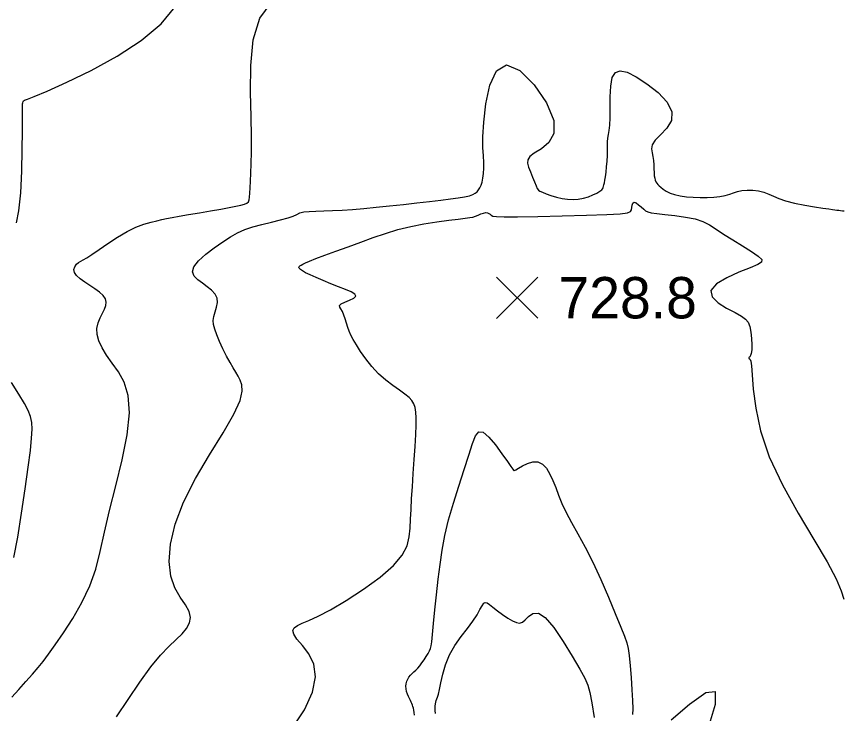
# Model space of a CAD drawing. Extents: x 2566142 to 2571431, y 418755 to 421584.
# Drawn here: x 2569642.8 to 2569942.6, y 420061.6 to 420314.2 of the extents above; entities that cross this region are included whole.
import ezdxf

# ---------------------------------------------------------------- set-up
doc = ezdxf.new("R2010")
doc.units = 0
for name, color, linetype in [('Contour_ADS_Major', 7, 'Continuous'), ('Contour_ADS_Minor', 7, 'Continuous'), ('Contour_ADS_Spot_Elevation', 7, 'Continuous')]:
    doc.layers.add(name, color=color, linetype=linetype)

# ---------------------------------------------------------------- blocks, each defined once
blk = doc.blocks.new('S750')
at = {"layer": 'Contour_ADS_Spot_Elevation'}
for p, q in [((-0.5, 0.498), (0.5, -0.498)), ((-0.498, -0.5), (0.498, 0.5))]:
    blk.add_line(p, q, dxfattribs=at)

msp = doc.modelspace()

# ---------------------------------------------------------------- linework, layer by layer
at = {"layer": 'Contour_ADS_Major'}
for points in [[(2569745.54, 420223.85), (2569745.97, 420224.12), (2569746.56, 420224.46), (2569747.51, 420224.92), (2569749.03, 420225.58), (2569751.35, 420226.5), (2569754.61, 420227.73), (2569758.61, 420229.2), (2569763.04, 420230.8), (2569767.63, 420232.46), (2569772.12, 420234.08), (2569776.57, 420235.6), (2569781.06, 420236.98), (2569785.7, 420238.17), (2569790.51, 420239.12), (2569795.22, 420239.87), (2569799.49, 420240.43), (2569802.98, 420240.83), (2569805.46, 420241.12), (2569807.12, 420241.34), (2569808.26, 420241.56), (2569809.2, 420241.85), (2569810.17, 420242.24), (2569811.17, 420242.65), (2569812.11, 420243), (2569812.93, 420243.18), (2569813.58, 420243.13), (2569814.09, 420242.89), (2569814.52, 420242.56), (2569814.94, 420242.2), (2569815.5, 420241.91), (2569816.81, 420241.69), (2569819.56, 420241.58), (2569824.46, 420241.59), (2569831.84, 420241.72), (2569840.64, 420241.95), (2569849.43, 420242.23), (2569856.78, 420242.51), (2569861.61, 420242.77), (2569864.26, 420243.08), (2569865.42, 420243.51), (2569865.76, 420244.13), (2569865.89, 420244.98), (2569866.01, 420245.87), (2569866.23, 420246.59), (2569866.68, 420246.91), (2569867.42, 420246.67), (2569868.35, 420246.03), (2569869.32, 420245.2), (2569870.19, 420244.4), (2569870.89, 420243.81), (2569871.68, 420243.39), (2569872.91, 420243.09), (2569874.92, 420242.81), (2569877.91, 420242.5), (2569881.54, 420242.1), (2569885.34, 420241.56), (2569888.82, 420240.84), (2569891.65, 420239.88), (2569894.07, 420238.67), (2569896.45, 420237.17), (2569899.18, 420235.37), (2569902.49, 420233.28), (2569906.02, 420231.09), (2569909.28, 420229.03), (2569911.75, 420227.32), (2569913.02, 420226.11), (2569912.96, 420225.2), (2569911.56, 420224.32), (2569908.77, 420223.17), (2569904.74, 420221.56), (2569900.33, 420219.55), (2569896.59, 420217.3), (2569894.56, 420214.95), (2569894.96, 420212.63), (2569897.17, 420210.45), (2569900.27, 420208.51), (2569903.33, 420206.89), (2569905.61, 420205.65), (2569907.12, 420204.57), (2569908.07, 420203.4), (2569908.65, 420201.88), (2569909.05, 420199.85), (2569909.3, 420197.53), (2569909.4, 420195.26), (2569909.35, 420193.36), (2569909.17, 420192.08), (2569908.91, 420191.33), (2569908.65, 420190.92), (2569908.44, 420190.7), (2569908.34, 420190.52), (2569908.35, 420190.35), (2569908.44, 420190.2), (2569908.59, 420190.09), (2569908.77, 420189.91), (2569909, 420189.25), (2569909.25, 420187.57), (2569909.54, 420184.35), (2569909.93, 420179.2), (2569910.8, 420172.31), (2569912.58, 420163.99)], [(2569742.59, 420056.01), (2569747.26, 420062.95), (2569750.15, 420069.3), (2569751.21, 420074.85), (2569750.54, 420079.48), (2569748.72, 420083.24), (2569746.46, 420086.23), (2569744.46, 420088.56), (2569743.31, 420090.33), (2569743.03, 420091.66), (2569743.5, 420092.67), (2569744.62, 420093.49), (2569746.31, 420094.28), (2569748.75, 420095.28), (2569752.12, 420096.82), (2569756.65, 420099.18), (2569762.36, 420102.54), (2569768.61, 420106.61), (2569774.59, 420110.97), (2569779.48, 420115.19), (2569782.67, 420118.97), (2569784.42, 420122.37), (2569785.2, 420125.57), (2569785.49, 420128.74), (2569785.67, 420132.04), (2569785.85, 420135.58), (2569786.05, 420139.47), (2569786.31, 420143.8), (2569786.63, 420148.61), (2569786.97, 420153.59), (2569787.29, 420158.4), (2569787.54, 420162.66), (2569787.67, 420166.1), (2569787.67, 420168.78), (2569787.53, 420170.86), (2569787.27, 420172.5), (2569786.84, 420173.83), (2569786.17, 420175), (2569785.14, 420176.13), (2569783.64, 420177.35), (2569781.63, 420178.77), (2569779.23, 420180.45), (2569776.64, 420182.41), (2569774.05, 420184.71), (2569771.62, 420187.33), (2569769.44, 420190.1), (2569767.56, 420192.8), (2569766.02, 420195.2), (2569764.86, 420197.14), (2569764.01, 420198.74), (2569763.38, 420200.15), (2569762.88, 420201.55), (2569762.42, 420203.05), (2569761.97, 420204.59), (2569761.49, 420206.03), (2569760.96, 420207.27), (2569760.38, 420208.21), (2569759.96, 420208.93), (2569759.93, 420209.51), (2569760.53, 420210.07), (2569761.88, 420210.69), (2569763.57, 420211.37), (2569765.07, 420212.09), (2569765.84, 420212.84), (2569765.5, 420213.62), (2569764.15, 420214.44), (2569762.08, 420215.33), (2569759.54, 420216.3), (2569756.78, 420217.37), (2569754.01, 420218.49), (2569751.43, 420219.57), (2569749.24, 420220.55), (2569747.58, 420221.37), (2569746.43, 420222.03), (2569745.7, 420222.57), (2569745.31, 420222.99), (2569745.17, 420223.32), (2569745.26, 420223.59), (2569745.54, 420223.85)], [(2569912.58, 420163.99), (2569915.74, 420154.57), (2569920.49, 420144.43), (2569926.16, 420134.22), (2569931.86, 420124.7), (2569936.68, 420116.58), (2569939.94, 420110.41), (2569941.85, 420106), (2569942.81, 420102.99)]]:
    msp.add_lwpolyline(points, dxfattribs=at)
at = {"layer": 'Contour_ADS_Minor'}
for points in [[(2569671.98, 420198.99), (2569671.95, 420201.18), (2569672.38, 420203.21), (2569673.1, 420205.06), (2569673.9, 420206.72), (2569674.64, 420208.19), (2569675.15, 420209.5), (2569675.32, 420210.73), (2569675.01, 420211.92), (2569674.14, 420213.11), (2569672.81, 420214.32), (2569671.17, 420215.54), (2569669.37, 420216.76), (2569667.56, 420217.97), (2569665.9, 420219.16), (2569664.58, 420220.33), (2569663.77, 420221.47), (2569663.6, 420222.55), (2569663.92, 420223.55), (2569664.56, 420224.41), (2569665.31, 420225.09), (2569666.05, 420225.58), (2569666.95, 420226.08), (2569668.23, 420226.81), (2569670.12, 420228.01), (2569672.76, 420229.82), (2569675.95, 420232.01), (2569679.42, 420234.27), (2569682.88, 420236.28), (2569686.1, 420237.82), (2569689, 420238.91), (2569691.55, 420239.66), (2569693.71, 420240.19), (2569695.5, 420240.6), (2569697.22, 420240.97), (2569699.19, 420241.35), (2569701.77, 420241.82), (2569705.17, 420242.41), (2569709.1, 420243.1), (2569713.13, 420243.8), (2569716.85, 420244.45), (2569719.92, 420244.99), (2569722.33, 420245.44), (2569724.14, 420245.82), (2569725.45, 420246.19), (2569726.32, 420246.56), (2569726.85, 420247.05), (2569727.15, 420247.76), (2569727.3, 420248.8), (2569727.41, 420250.26), (2569727.5, 420252.18), (2569727.59, 420254.57), (2569727.71, 420257.45), (2569727.85, 420260.88), (2569727.98, 420265.18), (2569728.01, 420270.72), (2569727.88, 420277.88), (2569727.63, 420286.76), (2569727.69, 420296.46), (2569728.63, 420305.82), (2569730.98, 420313.68), (2569735.06, 420319.16)], [(2569642.73, 420239.49), (2569643.68, 420243.74), (2569644.31, 420250.31), (2569644.67, 420258.19), (2569644.83, 420266.07), (2569644.89, 420272.64), (2569644.92, 420276.91), (2569644.92, 420279.22), (2569644.92, 420280.23), (2569644.92, 420280.61), (2569644.92, 420280.91), (2569644.92, 420281.25), (2569644.94, 420281.64), (2569644.96, 420282.07), (2569645, 420282.54), (2569645.06, 420283), (2569645.15, 420283.41), (2569645.31, 420283.7), (2569645.63, 420283.89), (2569646.72, 420284.29), (2569649.24, 420285.28), (2569653.89, 420287.24), (2569661.04, 420290.43), (2569669.88, 420294.71), (2569679.24, 420299.82), (2569688.01, 420305.51), (2569695.18, 420311.54), (2569700.36, 420317.74)], [(2569714.27, 420205.55), (2569714.75, 420207.16), (2569715.29, 420208.84), (2569715.63, 420210.53), (2569715.52, 420212.14), (2569714.77, 420213.62), (2569713.5, 420214.99), (2569711.9, 420216.28), (2569710.16, 420217.53), (2569708.48, 420218.78), (2569707.17, 420220.12), (2569706.58, 420221.66), (2569707.04, 420223.5), (2569708.75, 420225.68), (2569711.38, 420228.05), (2569714.48, 420230.42), (2569717.59, 420232.57), (2569720.36, 420234.35), (2569722.93, 420235.79), (2569725.54, 420236.98), (2569728.44, 420237.99), (2569731.78, 420238.9), (2569735.28, 420239.72), (2569738.56, 420240.48), (2569741.26, 420241.2), (2569743.12, 420241.89), (2569744.42, 420242.5), (2569745.56, 420243.02), (2569746.93, 420243.39), (2569748.85, 420243.61), (2569751.3, 420243.72), (2569754.19, 420243.78), (2569757.41, 420243.88), (2569760.89, 420244.06), (2569764.64, 420244.32), (2569768.73, 420244.68), (2569773.19, 420245.11), (2569778.03, 420245.61), (2569783.04, 420246.15), (2569787.97, 420246.7), (2569792.57, 420247.22), (2569796.63, 420247.68), (2569800.1, 420248.1), (2569802.98, 420248.49), (2569805.26, 420248.88), (2569806.97, 420249.28), (2569808.21, 420249.71), (2569809.1, 420250.18), (2569809.77, 420250.73), (2569810.34, 420251.36), (2569810.82, 420252.13), (2569811.24, 420253.07), (2569811.6, 420254.24), (2569811.91, 420255.66), (2569812.13, 420257.33), (2569812.25, 420259.24), (2569812.23, 420261.36), (2569812.08, 420263.74), (2569811.91, 420266.71), (2569811.89, 420270.63), (2569812.19, 420275.9), (2569812.96, 420282.56), (2569814.44, 420289.34), (2569816.88, 420294.6), (2569820.5, 420296.73), (2569825.33, 420294.66), (2569830.51, 420289.51), (2569834.95, 420282.93), (2569837.57, 420276.59), (2569837.63, 420271.81), (2569835.8, 420268.52), (2569833.09, 420266.3), (2569830.51, 420264.74), (2569828.86, 420263.47), (2569828.13, 420262.3), (2569828.07, 420261.07), (2569828.46, 420259.63), (2569829.09, 420257.9), (2569829.83, 420256.04), (2569830.56, 420254.28), (2569831.17, 420252.85), (2569831.61, 420251.91), (2569832, 420251.34), (2569832.55, 420250.94), (2569833.44, 420250.54), (2569834.81, 420250), (2569836.56, 420249.37), (2569838.54, 420248.75), (2569840.6, 420248.26), (2569842.61, 420247.97), (2569844.56, 420247.9), (2569846.45, 420248.05), (2569848.31, 420248.4), (2569850.12, 420248.93), (2569851.79, 420249.58), (2569853.23, 420250.26), (2569854.32, 420250.89), (2569855, 420251.41), (2569855.35, 420251.84), (2569855.51, 420252.25), (2569855.61, 420252.69)], [(2569855.61, 420252.69), (2569855.74, 420253.23), (2569855.92, 420253.93), (2569856.13, 420254.89), (2569856.35, 420256.18), (2569856.57, 420257.84), (2569856.76, 420259.77), (2569856.92, 420261.81), (2569857.02, 420263.81), (2569857.06, 420265.64), (2569857.06, 420267.3), (2569857.09, 420268.81), (2569857.2, 420270.18), (2569857.41, 420271.47), (2569857.66, 420272.93), (2569857.89, 420274.86), (2569858.02, 420277.53), (2569858.01, 420281.1), (2569858.02, 420285.11), (2569858.22, 420288.97), (2569858.81, 420292.08), (2569859.94, 420293.95), (2569861.71, 420294.57), (2569864.19, 420294.02), (2569867.43, 420292.4), (2569871.38, 420289.84), (2569875.38, 420286.64), (2569878.67, 420283.14), (2569880.45, 420279.68), (2569880.22, 420276.54), (2569878.57, 420273.79), (2569876.32, 420271.4), (2569874.35, 420269.37), (2569873.29, 420267.69), (2569873.02, 420266.24), (2569873.22, 420264.88), (2569873.56, 420263.51), (2569873.79, 420262.02), (2569873.89, 420260.48), (2569873.92, 420258.99), (2569873.96, 420257.65), (2569874.04, 420256.53), (2569874.18, 420255.63), (2569874.38, 420254.89), (2569874.62, 420254.3), (2569874.91, 420253.8), (2569875.29, 420253.34), (2569875.78, 420252.87), (2569876.44, 420252.32), (2569877.29, 420251.67), (2569878.38, 420250.95), (2569879.74, 420250.26), (2569881.41, 420249.66), (2569883.42, 420249.2), (2569885.69, 420248.9), (2569888.13, 420248.72), (2569890.65, 420248.64), (2569893.17, 420248.65), (2569895.59, 420248.76), (2569897.82, 420248.98), (2569899.76, 420249.32), (2569901.37, 420249.79), (2569902.79, 420250.32), (2569904.2, 420250.8), (2569905.79, 420251.16), (2569907.68, 420251.32), (2569909.76, 420251.27), (2569911.86, 420251), (2569913.81, 420250.53), (2569915.52, 420249.88), (2569917.2, 420249.09), (2569919.15, 420248.24), (2569921.67, 420247.38), (2569924.93, 420246.58), (2569928.58, 420245.87), (2569932.15, 420245.27), (2569935.17, 420244.81), (2569937.29, 420244.49), (2569938.65, 420244.29), (2569939.54, 420244.16), (2569940.22, 420244.08), (2569940.91, 420244.01), (2569941.61, 420243.94), (2569942.28, 420243.85), (2569942.87, 420243.75)], [(2569679.06, 420060.39), (2569683.32, 420066.68), (2569687.53, 420072.92), (2569691.49, 420078.43), (2569695, 420082.71), (2569698.06, 420085.91), (2569700.65, 420088.38), (2569702.79, 420090.45), (2569704.47, 420092.41), (2569705.55, 420094.38), (2569705.92, 420096.41), (2569705.42, 420098.56), (2569704.03, 420100.93), (2569702.13, 420103.71), (2569700.19, 420107.12), (2569698.7, 420111.39), (2569698.09, 420116.69), (2569698.57, 420122.98), (2569700.26, 420130.16), (2569703.32, 420138.14), (2569707.73, 420146.74), (2569712.8, 420155.37), (2569717.7, 420163.37), (2569721.58, 420170.08), (2569723.82, 420175.02), (2569724.64, 420178.43), (2569724.5, 420180.76), (2569723.86, 420182.45), (2569723.1, 420183.88), (2569722.25, 420185.29), (2569721.29, 420186.86), (2569720.19, 420188.78), (2569718.94, 420191.15), (2569717.64, 420193.79), (2569716.41, 420196.46), (2569715.37, 420198.88), (2569714.63, 420200.88), (2569714.19, 420202.55), (2569714.07, 420204.06), (2569714.27, 420205.55)], [(2569641.09, 420067.44), (2569643.63, 420070.3), (2569646.21, 420073.19), (2569648.58, 420075.86), (2569650.59, 420078.19), (2569652.44, 420080.46), (2569654.41, 420083.07), (2569656.81, 420086.42), (2569659.83, 420090.8), (2569663.17, 420096.01), (2569666.47, 420101.79), (2569669.33, 420107.81), (2569671.49, 420113.91), (2569673.17, 420120.29), (2569674.73, 420127.27), (2569676.52, 420135.16), (2569678.74, 420144.1), (2569681.03, 420153.49), (2569682.87, 420162.56), (2569683.74, 420170.53), (2569683.29, 420176.81), (2569681.8, 420181.64), (2569679.71, 420185.42), (2569677.46, 420188.57), (2569675.44, 420191.45), (2569673.79, 420194.14), (2569672.61, 420196.64), (2569671.98, 420198.99)], [(2569641.85, 420118.14), (2569643.22, 420125.51), (2569644.62, 420134.18), (2569645.93, 420143.02), (2569647.02, 420150.9), (2569647.81, 420156.96), (2569648.27, 420161.38), (2569648.43, 420164.59), (2569648.29, 420167.05), (2569647.84, 420169.18), (2569646.99, 420171.36), (2569645.62, 420173.94), (2569643.62, 420177.29), (2569640.97, 420181.61)], [(2569787.11, 420060.95), (2569787.02, 420061.92), (2569786.88, 420062.74), (2569786.71, 420063.46), (2569786.51, 420064.08), (2569786.31, 420064.64), (2569786.1, 420065.17), (2569785.87, 420065.71), (2569785.6, 420066.28), (2569785.29, 420066.95), (2569784.92, 420067.72), (2569784.55, 420068.58), (2569784.23, 420069.51), (2569784.01, 420070.47), (2569783.95, 420071.43), (2569784.05, 420072.37), (2569784.28, 420073.25), (2569784.63, 420074.06), (2569785.09, 420074.77), (2569785.64, 420075.41), (2569786.25, 420076.02), (2569786.9, 420076.64), (2569787.58, 420077.3), (2569788.29, 420078.05), (2569789.03, 420078.9), (2569789.8, 420079.88), (2569790.59, 420081.01), (2569791.36, 420082.2), (2569792.04, 420083.33), (2569792.57, 420084.3), (2569792.93, 420085.08), (2569793.16, 420086.04), (2569793.36, 420087.6), (2569793.62, 420090.21), (2569794.01, 420094.15), (2569794.51, 420099.11), (2569795.08, 420104.63), (2569795.7, 420110.24), (2569796.35, 420115.6), (2569797.12, 420120.81), (2569798.12, 420126.12), (2569799.47, 420131.75), (2569801.22, 420137.83), (2569803.19, 420144.04), (2569805.14, 420149.97), (2569806.84, 420155.22), (2569808.13, 420159.39), (2569809.21, 420162.29), (2569810.38, 420163.74), (2569811.93, 420163.58), (2569814.03, 420161.78), (2569816.44, 420158.93), (2569818.8, 420155.74), (2569820.75, 420152.96), (2569822.02, 420151.13), (2569822.71, 420150.15), (2569823.01, 420149.74)], [(2569823.01, 420149.74), (2569823.11, 420149.63), (2569823.19, 420149.6), (2569823.4, 420149.68), (2569823.89, 420149.95), (2569824.8, 420150.49), (2569826.23, 420151.33), (2569828.02, 420152.22), (2569829.97, 420152.82), (2569831.85, 420152.83), (2569833.51, 420152), (2569834.94, 420150.45), (2569836.19, 420148.39), (2569837.28, 420145.99), (2569838.29, 420143.44), (2569839.33, 420140.7), (2569840.55, 420137.72), (2569842.08, 420134.44), (2569844.03, 420130.79), (2569846.35, 420126.66), (2569848.94, 420121.91), (2569851.74, 420116.43), (2569854.62, 420110.2), (2569857.4, 420103.77), (2569859.89, 420097.79), (2569861.88, 420092.91), (2569863.22, 420089.57), (2569864.05, 420087.24), (2569864.55, 420085.15), (2569864.91, 420082.55), (2569865.26, 420078.9), (2569865.61, 420074.57), (2569865.91, 420070.15), (2569866.12, 420066.24), (2569866.2, 420063.28), (2569866.19, 420061.18)], [(2569794.72, 420061.58), (2569794.63, 420062.6), (2569794.59, 420063.46), (2569794.6, 420064.27), (2569794.68, 420065.03), (2569794.81, 420065.71), (2569794.99, 420066.3), (2569795.21, 420066.83), (2569795.48, 420067.5), (2569795.81, 420068.55), (2569796.2, 420070.23), (2569796.67, 420072.7), (2569797.34, 420075.79), (2569798.33, 420079.25), (2569799.78, 420082.8), (2569801.74, 420086.23), (2569804.01, 420089.45), (2569806.28, 420092.42), (2569808.27, 420095.07), (2569809.76, 420097.36), (2569810.82, 420099.23), (2569811.58, 420100.63), (2569812.19, 420101.51), (2569812.76, 420101.84), (2569813.43, 420101.66), (2569814.32, 420101.04), (2569815.54, 420100.06), (2569817.17, 420098.81), (2569819.03, 420097.45), (2569820.93, 420096.16), (2569822.65, 420095.13), (2569824.03, 420094.51), (2569825.17, 420094.35), (2569826.19, 420094.68), (2569827.25, 420095.52), (2569828.48, 420096.77), (2569830.02, 420097.82), (2569831.99, 420097.94), (2569834.52, 420096.38), (2569837.65, 420092.72), (2569841.05, 420087.69), (2569844.3, 420082.31), (2569846.98, 420077.62), (2569848.79, 420074.32), (2569849.91, 420071.81), (2569850.66, 420069.18), (2569851.35, 420065.49), (2569852.22, 420060.12)], [(2569880.1, 420059.3), (2569886.8, 420064.96), (2569892.68, 420069.14), (2569896.15, 420069.59), (2569896.14, 420064.82), (2569893.54, 420056.42)]]:
    msp.add_lwpolyline(points, dxfattribs=at)

# ---------------------------------------------------------------- block references
at = {"layer": 'Contour_ADS_Spot_Elevation', "xscale": 15, "yscale": 15}
msp.add_blockref('S750', (2569824.29, 420212.3), dxfattribs=at)

# ---------------------------------------------------------------- texts
at = {"layer": 'Contour_ADS_Spot_Elevation'}
msp.add_text('728.8', height=15, dxfattribs=at).set_placement((2569839.29, 420204.8))

doc.saveas('drawing.dxf')
